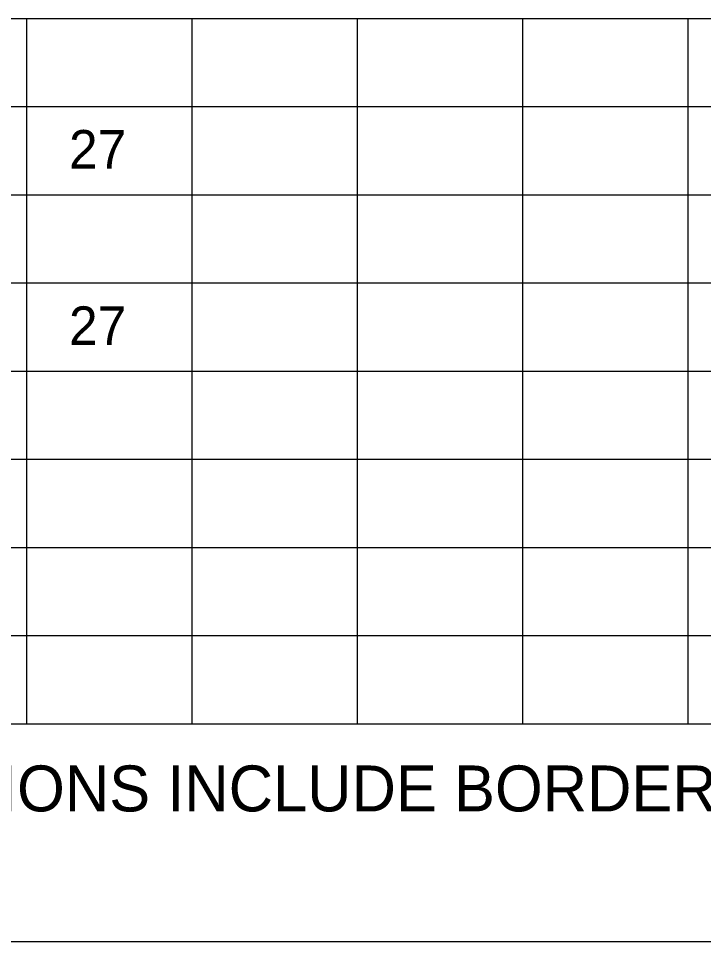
# Model space of a CAD drawing. Extents: x 10268312 to 10268706, y 2142548 to 2142786.
# Drawn here: x 10268407.83 to 10268420.26, y 2142640.28 to 2142657.03 of the extents above; entities that cross this region are included whole.
import ezdxf

# ---------------------------------------------------------------- set-up
doc = ezdxf.new("R2010")
doc.units = 0
for name, color, linetype in [('SheetBorder_dp', 7, 'Continuous'), ('SumBoxLines_dp', 7, 'Continuous'), ('SumBoxLinesMin_dp', 7, 'Continuous'), ('TextLabel', 7, 'Continuous'), ('TextNotes', 7, 'Continuous')]:
    doc.layers.add(name, color=color, linetype=linetype)

msp = doc.modelspace()

# ---------------------------------------------------------------- linework, layer by layer
at = {"layer": 'SheetBorder_dp'}
msp.add_line((10268317.73, 2142640.282), (10268471.73, 2142640.282), dxfattribs=at)
at = {"layer": 'SumBoxLines_dp'}
for p, q in [((10268395.48, 2142657.032), (10268470.98, 2142657.032)), ((10268407.98, 2142657.032), (10268407.98, 2142653.832)), ((10268410.98, 2142657.032), (10268410.98, 2142653.832)), ((10268413.98, 2142657.032), (10268413.98, 2142653.832)), ((10268416.98, 2142657.032), (10268416.98, 2142653.832)), ((10268419.98, 2142657.032), (10268419.98, 2142655.432)), ((10268419.98, 2142655.432), (10268419.98, 2142650.632)), ((10268395.48, 2142653.832), (10268470.98, 2142653.832)), ((10268407.98, 2142653.832), (10268407.98, 2142647.432)), ((10268410.98, 2142653.832), (10268410.98, 2142647.432)), ((10268413.98, 2142653.832), (10268413.98, 2142647.432)), ((10268416.98, 2142653.832), (10268416.98, 2142650.632)), ((10268395.48, 2142650.632), (10268470.98, 2142650.632)), ((10268416.98, 2142650.632), (10268416.98, 2142647.432)), ((10268419.98, 2142650.632), (10268419.98, 2142647.432)), ((10268395.48, 2142647.432), (10268470.98, 2142647.432)), ((10268407.98, 2142647.432), (10268407.98, 2142644.232)), ((10268410.98, 2142647.432), (10268410.98, 2142644.232)), ((10268413.98, 2142647.432), (10268413.98, 2142644.232)), ((10268416.98, 2142647.432), (10268416.98, 2142644.232)), ((10268419.98, 2142647.432), (10268419.98, 2142644.232)), ((10268395.48, 2142644.232), (10268470.98, 2142644.232))]:
    msp.add_line(p, q, dxfattribs=at)
at = {"layer": 'SumBoxLinesMin_dp'}
for p, q in [((10268395.48, 2142655.432), (10268470.98, 2142655.432)), ((10268395.48, 2142652.232), (10268470.98, 2142652.232)), ((10268395.48, 2142649.032), (10268470.98, 2142649.032)), ((10268395.48, 2142645.832), (10268470.98, 2142645.832))]:
    msp.add_line(p, q, dxfattribs=at)

# ---------------------------------------------------------------- texts
at = {"layer": 'TextLabel'}
for p in [(10268408.751, 2142654.307), (10268408.751, 2142651.107)]:
    msp.add_text('27', height=0.7, dxfattribs=at).set_placement(p)
at = {"layer": 'TextNotes'}
msp.add_text('NOTE:  END DIMENSIONS INCLUDE BORDER WIDTH, MARGIN AND BORDER RECESS.  ', height=0.83333, dxfattribs=at).set_placement((10268396.479, 2142642.643))

doc.saveas('drawing.dxf')
